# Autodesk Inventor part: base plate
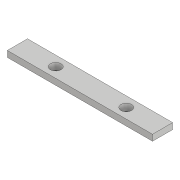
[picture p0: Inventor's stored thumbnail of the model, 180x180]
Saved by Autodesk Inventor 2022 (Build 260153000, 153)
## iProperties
Created: 2016-03
Part Number: base plate
Material: Generic
Document SubType Name: Modeling
Designer: Sandeep
Density: 1 g/cm^3
Appearance: Default
Mass: 16.6527 g
Surface Area: 78.2446 cm^2
Volume: 16.6527 cm^3
Author: Sandeep
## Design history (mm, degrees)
sketch "Sketch1"
  geometry: L1 (0, 0)-(144, 0); L2 (144, 0)-(144, 20); L3 (144, 20)-(0, 20); L4 (0, 20)-(0, 0)
  constraints: 8 end point, 2 parallel, 1 horizontal, 1 perpendicular
  dimensions: "d0" = 144 distance of L1.start L1.end; "d1" = 20 distance of L1.end L2.end
extrude "Extrusion1" new body sketch "Sketch1" distance "d2" = 6; taper "d3" = 0 deg
sketch "Sketch2"
  geometry: L1 (0, 20)-(0, 0) reference; L2 (0, 10)-(181.292, 10); 2 further points
  constraints: 2 end point, 2 point on line, 1 horizontal, 1 midpoint
  dimensions: "d4" = 70 distance of point (108, 10) point (38, 10); "d5" = 38 distance from line of L1 point (38, 10)
hole "Hole1" sketch "Sketch2" at (38, 10), (108, 10) diameter "d6" = 6; stored, may be unused: countersink angle "d10" = 45 deg, drill point angle "d12" = 118 deg; dims "d7" = 6, "d8" = 10.5, "d9" = 2, "d11" = 8
body "Solid1"
